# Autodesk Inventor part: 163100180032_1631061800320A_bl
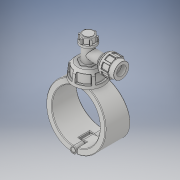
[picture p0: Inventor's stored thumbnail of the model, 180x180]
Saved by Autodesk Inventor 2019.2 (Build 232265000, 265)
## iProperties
Created: 2022-02
Part Number: 163100180032_1631061800320A_bl
Material: Generic
Description: Plassadle Tapper 160x32
Document SubType Name: Modeling
Designer: comp2
Density: 1 g/cm^3
Appearance: Default
Author: comp2
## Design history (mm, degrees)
derived "16310.ipt"
feature "Solid1::16310.ipt" dims "ScaleForDerivedMember" = 10
feature "Solid2::16310.ipt" dims "ScaleForDerivedMember" = 10
feature "Solid3::16310.ipt" dims "ScaleForDerivedMember" = 10
feature "Solid4::16310.ipt" dims "ScaleForDerivedMember" = 10
tag "TaggingFeature1"
body "Solid1"
body "Solid2"
body "Solid3"
body "Solid4"
other parameters: "d2" = 198 [user parameter], "d5" = 325 [user parameter], "d7" = 188.1 [user parameter], "d8" = 85 deg [user parameter], "d9" = 45 deg [user parameter], "d10" = 102 [user parameter], "d11" = 49 [user parameter], "d12" = 34.3 [user parameter], "d13" = 35.7 [user parameter], "d14" = 55.08 [user parameter], "d15" = 2.45 [user parameter], "d16" = 2 [user parameter], "d17" = 2 [user parameter], "d18" = 29.4 [user parameter], "d19" = 7.35 [user parameter], "d20" = 1 [user parameter], "d21" = 30.6 [user parameter], "d22" = 1 [user parameter], "d23" = 14.7 [user parameter], "d24" = 111 [user parameter], "d27" = 144 [user parameter], "d29" = 64 [user parameter], "d31" = 51.2 [user parameter], "d32" = 44.4 [user parameter], "d33" = 15.54 [user parameter], "d34" = 93 deg [user parameter], "d35" = 2 [user parameter], "d36" = 4 [user parameter], "d39" = 45 deg [user parameter], "d40" = 4 [user parameter], "d41" = 5 [user parameter], "d42" = 3.8 [user parameter], "d46" = 51 [user parameter], "d47" = 32 [user parameter], "d48" = 49 [user parameter], "d49" = 3.96 [user parameter], "d50" = 106 [user parameter], "d51" = 0 [user parameter], "d52" = 26.6 [user parameter], "d53" = 108.9 [user parameter], "d54" = 37.1 [user parameter], "d55" = 0 [user parameter], "d56" = 21.2 [user parameter], "d57" = 21.2 [user parameter], "d59" = 0 [user parameter], "d60" = 106 [user parameter], "d61" = 0 [user parameter], "d62" = 37.1 [user parameter], "d63" = 0 [user parameter], "d65" = 0 [user parameter], "d67" = 0 [user parameter], "d69" = 0 [user parameter], "d70" = 1 [user parameter], "d71" = 101.76 [user parameter], "d72" = 0 [user parameter], "d73" = 2 [user parameter], "d77" = 32 [user parameter], "d78" = 86.7 [user parameter], "d79" = 5.1 [user parameter], "d80" = 60 deg [user parameter], "d81" = 5.1 [user parameter], "d84" = 0 [user parameter], "d85" = 1 [user parameter], "d87" = 360 deg [user parameter], "d90" = 0 [user parameter], "d91" = 1 [user parameter], "d93" = 60 deg [user parameter], "d94" = 3.06 [user parameter], "d95" = 3.06 [user parameter], "d97" = 0 [user parameter], "d98" = 0.5 [user parameter], "d100" = 360 deg [user parameter], "d102" = 2 [user parameter], "d105" = 0 [user parameter], "d106" = 45 deg [user parameter], "d107" = 3.2 [user parameter], "d108" = 3.2 [user parameter], "d109" = 2.95332 [user parameter], "d110" = -8 [user parameter], "d112" = 0 [user parameter], "d113" = 0.5 [user parameter], "d115" = 360 deg [user parameter], "d117" = 0.5 [user parameter], "d1" = 32 [user parameter], "B" = 198 [user parameter], "L" = 106 [user parameter], "E_" = 64 [user parameter], "E1" = 102 [user parameter], "H1" = 325 [user parameter], "H2" = 144 [user parameter], "H3" = 111 [user parameter], "H_costum" = 49 [user parameter]
